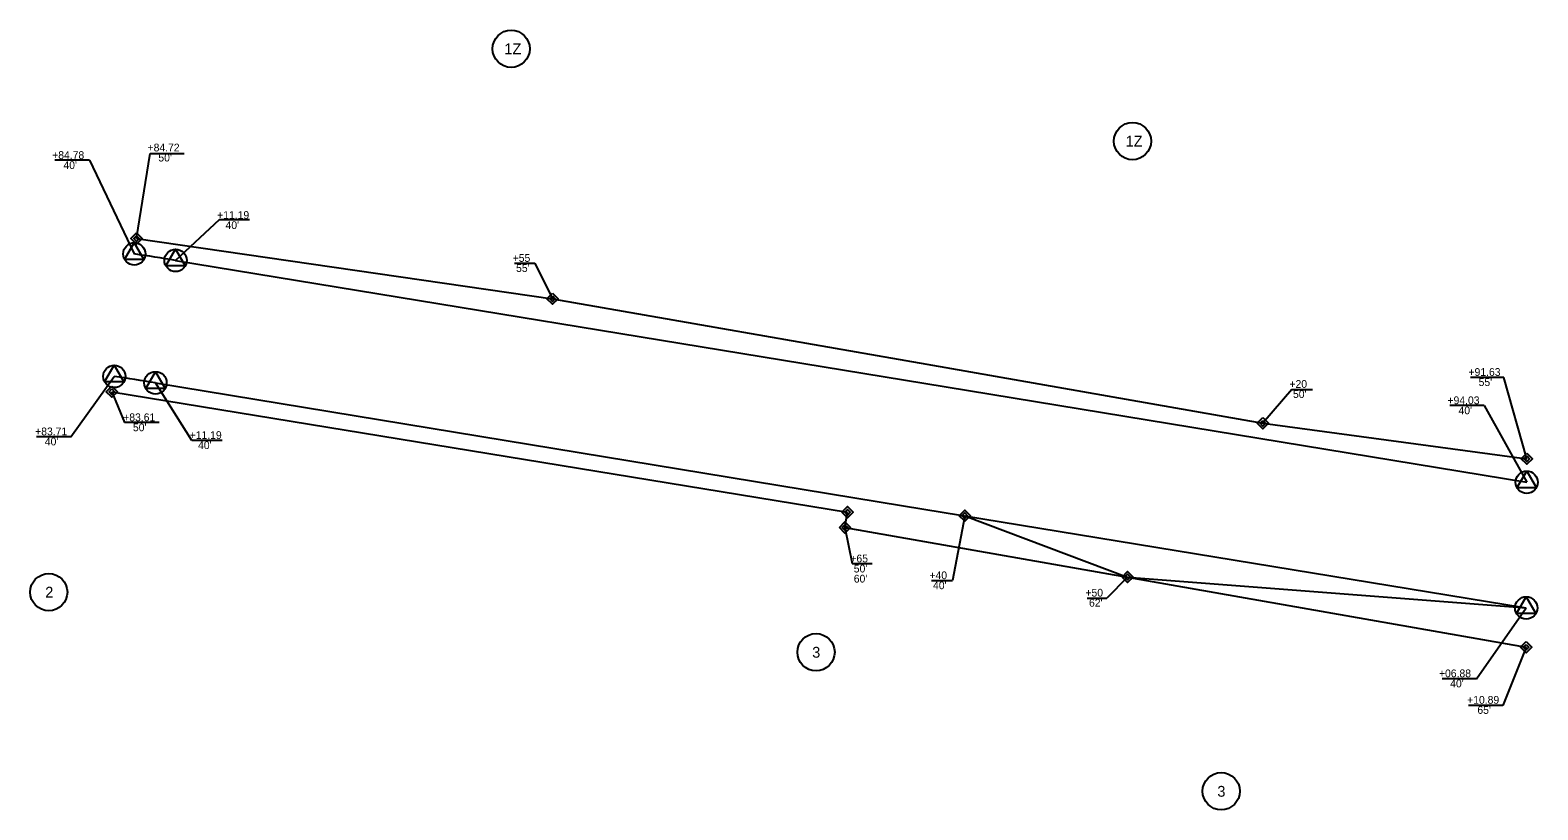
# Model space of a CAD drawing. Extents: x 1756120 to 1760612, y 736784 to 737319.
# Drawn here: x 1756120 to 1757093, y 736816 to 737319 of the extents above; entities that cross this region are included whole.
import ezdxf

# ---------------------------------------------------------------- set-up
doc = ezdxf.new("R2010")
doc.units = 0
for name, color, linetype in [('Prop Easement Permanent Drainage Utility', 7, 'Continuous'), ('Prop Easement Permanent Drainage Utility Station Offsets', 7, 'Continuous'), ('Prop Easement Permanent Utility', 7, 'Continuous'), ('Prop Easement Permanent Utility Station Offsets', 7, 'Continuous'), ('Prop Parcel Number CELL', 7, 'Continuous'), ('Prop Parcel Number Text', 7, 'Continuous'), ('Prop ROW Marker CELL', 7, 'Continuous'), ('Prop ROW Permanent Easement CELL', 7, 'Continuous'), ('Prop ROW RW Lines', 7, 'Continuous'), ('Prop ROW Station Offsets', 7, 'Continuous')]:
    doc.layers.add(name, color=color, linetype=linetype)

msp = doc.modelspace()

# ---------------------------------------------------------------- linework, layer by layer
at = {"layer": 'Prop Easement Permanent Drainage Utility'}
for p, q in [((1756723.12, 737005.53), (1756828.11, 736966)), ((1756828.11, 736966), (1757085.16, 736946.1))]:
    msp.add_line(p, q, dxfattribs=at)
at = {"layer": 'Prop Easement Permanent Drainage Utility Station Offsets'}
for p, q in [((1756723.12, 737005.53), (1756715.19, 736963.72)), ((1756701.65, 736963.72), (1756715.19, 736963.72)), ((1756828.11, 736966), (1756814.71, 736952.39)), ((1756802.04, 736952.39), (1756814.71, 736952.39))]:
    msp.add_line(p, q, dxfattribs=at)
at = {"layer": 'Prop Easement Permanent Utility'}
for p, q in [((1756189.04, 737184.22), (1756457.28, 737145.44)), ((1756457.28, 737145.44), (1756698.67, 737103.15)), ((1756698.67, 737103.15), (1756915.33, 737065.18)), ((1756173.15, 737085.48), (1756647.5, 737007.81)), ((1756915.33, 737065.18), (1757085.5, 737042.32)), ((1756645.88, 736997.94), (1756647.5, 737007.81)), ((1756645.88, 736997.94), (1756828.11, 736966)), ((1756828.11, 736966), (1757085.07, 736920.78))]:
    msp.add_line(p, q, dxfattribs=at)
at = {"layer": 'Prop Easement Permanent Utility Station Offsets'}
for p, q in [((1756189.04, 737184.22), (1756197.89, 737239.05)), ((1756197.89, 737239.05), (1756219.85, 737239.05)), ((1756432.7, 737168.36), (1756445.92, 737168.36)), ((1756445.92, 737168.36), (1756457.28, 737145.44)), ((1757070.77, 737094.68), (1757049.22, 737094.68)), ((1757085.5, 737042.32), (1757070.77, 737094.68)), ((1756173.15, 737085.48), (1756181.38, 737065.75)), ((1756933.96, 737086.96), (1756915.33, 737065.18)), ((1756933.96, 737086.96), (1756947.44, 737086.96)), ((1756203.68, 737065.75), (1756181.38, 737065.75)), ((1756645.88, 736997.94), (1756650.42, 736974.65)), ((1756650.42, 736974.65), (1756663.33, 736974.65)), ((1757085.07, 736920.78), (1757070.11, 736883.23)), ((1757070.11, 736883.23), (1757047.87, 736883.23))]:
    msp.add_line(p, q, dxfattribs=at)
at = {"layer": 'Prop Parcel Number CELL'}
for centre in [(1756430.64, 737306.58), (1756831.27, 737247.05), (1756132.48, 736956.27), (1756627.23, 736917.56), (1756888.48, 736827.93)]:
    msp.add_circle(centre, 12, dxfattribs=at)
at = {"layer": 'Prop ROW Marker CELL'}
for p, q in [((1756189.04, 737184.22), (1756189.04, 737184.22)), ((1756187.62, 737174.32), (1756187.62, 737174.32)), ((1756214.26, 737170.14), (1756214.26, 737170.14)), ((1756457.28, 737145.44), (1756457.28, 737145.44)), ((1756174.72, 737095.36), (1756174.72, 737095.36)), ((1756173.15, 737085.48), (1756173.15, 737085.48)), ((1756201.3, 737091.19), (1756201.3, 737091.19)), ((1756915.33, 737065.18), (1756915.33, 737065.18)), ((1757085.5, 737042.32), (1757085.5, 737042.32)), ((1757085.44, 737027.12), (1757085.44, 737027.12)), ((1756647.5, 737007.81), (1756647.5, 737007.81)), ((1756645.88, 736997.94), (1756645.88, 736997.94)), ((1756723.12, 737005.53), (1756723.12, 737005.53)), ((1756828.11, 736966), (1756828.11, 736966)), ((1757085.16, 736946.1), (1757085.16, 736946.1)), ((1757085.07, 736920.78), (1757085.07, 736920.78))]:
    msp.add_line(p, q, dxfattribs=at)
for points in [[(1756181.37, 737170.72), (1756187.62, 737181.52), (1756193.87, 737170.72)], [(1756208.01, 737166.54), (1756214.26, 737177.34), (1756220.51, 737166.54)], [(1756168.47, 737091.76), (1756174.72, 737102.56), (1756180.97, 737091.76)], [(1756195.05, 737087.59), (1756201.3, 737098.39), (1756207.55, 737087.59)], [(1757079.19, 737023.52), (1757085.44, 737034.32), (1757091.69, 737023.52)], [(1757078.91, 736942.5), (1757085.16, 736953.3), (1757091.41, 736942.5)]]:
    msp.add_lwpolyline(points, close=True, dxfattribs=at)
for centre in [(1756187.62, 737174.32), (1756214.26, 737170.14), (1756174.72, 737095.36), (1756201.3, 737091.19), (1757085.44, 737027.12), (1757085.16, 736946.1)]:
    msp.add_circle(centre, 7.2, dxfattribs=at)
at = {"layer": 'Prop ROW Permanent Easement CELL'}
for points in [[(1756189.04, 737187.82), (1756192.64, 737184.22), (1756189.04, 737180.62), (1756185.44, 737184.22)], [(1756189.04, 737186.02), (1756190.84, 737184.22), (1756189.04, 737182.42), (1756187.24, 737184.22)], [(1756457.28, 737149.04), (1756460.88, 737145.44), (1756457.28, 737141.84), (1756453.68, 737145.44)], [(1756457.28, 737147.24), (1756459.08, 737145.44), (1756457.28, 737143.64), (1756455.48, 737145.44)], [(1756173.15, 737089.08), (1756176.75, 737085.48), (1756173.15, 737081.88), (1756169.55, 737085.48)], [(1756173.15, 737087.28), (1756174.95, 737085.48), (1756173.15, 737083.68), (1756171.35, 737085.48)], [(1756915.33, 737068.78), (1756918.93, 737065.18), (1756915.33, 737061.58), (1756911.73, 737065.18)], [(1756915.33, 737066.98), (1756917.13, 737065.18), (1756915.33, 737063.38), (1756913.53, 737065.18)], [(1757085.5, 737045.92), (1757089.1, 737042.32), (1757085.5, 737038.72), (1757081.9, 737042.32)], [(1757085.5, 737044.12), (1757087.3, 737042.32), (1757085.5, 737040.52), (1757083.7, 737042.32)], [(1756643.9, 737007.81), (1756647.5, 737011.41), (1756651.09, 737007.81), (1756647.5, 737004.21)], [(1756645.7, 737007.81), (1756647.5, 737009.61), (1756649.29, 737007.81), (1756647.5, 737006.01)], [(1756719.52, 737005.53), (1756723.12, 737009.13), (1756726.72, 737005.53), (1756723.12, 737001.93)], [(1756721.32, 737005.53), (1756723.12, 737007.33), (1756724.92, 737005.53), (1756723.12, 737003.73)], [(1756642.28, 736997.94), (1756645.88, 737001.54), (1756649.47, 736997.94), (1756645.88, 736994.34)], [(1756644.08, 736997.94), (1756645.88, 736999.74), (1756647.67, 736997.94), (1756645.88, 736996.14)], [(1756824.51, 736966), (1756828.11, 736969.6), (1756831.71, 736966), (1756828.11, 736962.4)], [(1756826.31, 736966), (1756828.11, 736967.8), (1756829.91, 736966), (1756828.11, 736964.2)], [(1757085.07, 736924.38), (1757088.67, 736920.78), (1757085.07, 736917.18), (1757081.47, 736920.78)], [(1757085.07, 736922.58), (1757086.87, 736920.78), (1757085.07, 736918.98), (1757083.27, 736920.78)]]:
    msp.add_lwpolyline(points, close=True, dxfattribs=at)
at = {"layer": 'Prop ROW RW Lines'}
for p, q in [((1756214.26, 737170.14), (1756696.66, 737090.95)), ((1756201.3, 737091.19), (1756683.6, 737012.02)), ((1756696.66, 737090.95), (1757085.44, 737027.12)), ((1756683.6, 737012.02), (1757085.16, 736946.1))]:
    msp.add_line(p, q, dxfattribs=at)
for radius, end in [(1937, 81.47506), (1857, 81.50744)]:
    msp.add_arc((1755900.48, 735258.72), radius, 80.67753, end, dxfattribs=at)
at = {"layer": 'Prop ROW Station Offsets'}
for p, q in [((1756158.64, 737234.81), (1756136.31, 737234.81)), ((1756262, 737196.26), (1756242.27, 737196.26)), ((1757058.12, 737076.62), (1757035.97, 737076.62)), ((1756146.74, 737056.46), (1756124.57, 737056.46)), ((1756244.19, 737054.1), (1756224.67, 737054.1)), ((1757053.07, 736900.35), (1757030.84, 736900.35))]:
    msp.add_line(p, q, dxfattribs=at)
for points in [[(1756158.64, 737234.81), (1756187.62, 737174.32)], [(1756242.27, 737196.26), (1756214.26, 737170.14)], [(1756146.74, 737056.46), (1756174.72, 737095.36)], [(1756224.67, 737054.1), (1756201.3, 737091.19)], [(1757058.12, 737076.62), (1757085.44, 737027.12)], [(1757053.07, 736900.35), (1757085.16, 736946.1)]]:
    msp.add_lwpolyline(points, dxfattribs=at)

# ---------------------------------------------------------------- texts
at = {"layer": 'Prop Easement Permanent Drainage Utility Station Offsets'}
for s, p in [('+40', (1756700.36, 736964.65)), ("40'", (1756702.65, 736958.15)), ('+50', (1756800.93, 736953.41)), ("62'", (1756803.22, 736946.91))]:
    msp.add_text(s, height=5, rotation=0.00001, dxfattribs=at).set_placement(p)
at = {"layer": 'Prop Easement Permanent Utility Station Offsets'}
for s, p in [('+84.72', (1756196.2, 737240.41)), ("50'", (1756203.16, 737233.91)), ('+55', (1756431.63, 737169.21)), ("55'", (1756433.81, 737162.71)), ('+20', (1756932.49, 737087.97)), ("50'", (1756934.77, 737081.47)), ('+65', (1756649.37, 736975.47)), ("50'", (1756651.56, 736968.97)), ("60'", (1756651.56, 736962.47))]:
    msp.add_text(s, height=5, rotation=0.00001, dxfattribs=at).set_placement(p)
for s, p in [('+91.63', (1757047.93, 737095.68)), ("55'", (1757054.45, 737089.18)), ('+83.61', (1756180.51, 737066.5)), ("50'", (1756186.75, 737060)), ('+10.89', (1757047.07, 736884.33)), ("65'", (1757053.66, 736877.83))]:
    msp.add_text(s, height=5, dxfattribs=at).set_placement(p)
at = {"layer": 'Prop Parcel Number Text'}
for s, p in [('1Z', (1756426.24, 737303.02)), ('1Z', (1756826.87, 737243.5)), ('2', (1756130.21, 736952.71)), ('3', (1756624.74, 736914.01)), ('3', (1756885.99, 736824.38))]:
    msp.add_text(s, height=7, rotation=0.00001, dxfattribs=at).set_placement(p)
at = {"layer": 'Prop ROW Station Offsets'}
for s, p in [('+84.78', (1756134.69, 737235.56)), ("40'", (1756141.92, 737229.06)), ('+11.19', (1756241.07, 737196.87)), ("40'", (1756246.47, 737190.37)), ('+94.03', (1757034.39, 737077.45)), ("40'", (1757041.51, 737070.95)), ('+83.71', (1756123.7, 737057.39)), ("40'", (1756129.94, 737050.89)), ('+11.19', (1756223.35, 737055.03)), ("40'", (1756228.74, 737048.53)), ('+06.88', (1757028.9, 736901.42)), ("40'", (1757036.13, 736894.92))]:
    msp.add_text(s, height=5, dxfattribs=at).set_placement(p)

doc.saveas('drawing.dxf')
